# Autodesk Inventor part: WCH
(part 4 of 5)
hole "Díra1578" diameter "d14201" = 3.52941; stored, may be unused: countersink angle "d14205" = 90 deg, drill point angle "d14207" = 0 deg; dims "d14199" = 21, "d14200" = 241, "d14202" = 6, "d14203" = 4, "d14204" = 2, "d14206" = 8
hole "Díra1579" diameter "d14210" = 3.76471; stored, may be unused: countersink angle "d14214" = 90 deg, drill point angle "d14216" = 0 deg; dims "d14208" = 32, "d14209" = 241, "d14211" = 6, "d14212" = 4, "d14213" = 2, "d14215" = 8
hole "Díra1580" diameter "d14219" = 4.82353; stored, may be unused: countersink angle "d14223" = 90 deg, drill point angle "d14225" = 0 deg; dims "d14217" = 43, "d14218" = 241, "d14220" = 6, "d14221" = 4, "d14222" = 2, "d14224" = 8
hole "Díra1581" diameter "d14228" = 2.19608; stored, may be unused: countersink angle "d14232" = 90 deg, drill point angle "d14234" = 0 deg; dims "d14226" = 54, "d14227" = 241, "d14229" = 6, "d14230" = 4, "d14231" = 2, "d14233" = 8
hole "Díra1582" diameter "d14237" = 1.05882; stored, may be unused: countersink angle "d14241" = 90 deg, drill point angle "d14243" = 0 deg; dims "d14235" = 65, "d14236" = 241, "d14238" = 6, "d14239" = 4, "d14240" = 2, "d14242" = 8
hole "Díra1583" diameter "d14246" = 5.88235; stored, may be unused: countersink angle "d14250" = 90 deg, drill point angle "d14252" = 0 deg; dims "d14244" = 76, "d14245" = 241, "d14247" = 6, "d14248" = 4, "d14249" = 2, "d14251" = 8
hole "Díra1584" diameter "d14255" = 7.37255; stored, may be unused: countersink angle "d14259" = 90 deg, drill point angle "d14261" = 0 deg; dims "d14253" = 87, "d14254" = 241, "d14256" = 6, "d14257" = 4, "d14258" = 2, "d14260" = 8
hole "Díra1585" diameter "d14264" = 5.4902; stored, may be unused: countersink angle "d14268" = 90 deg, drill point angle "d14270" = 0 deg; dims "d14262" = 98, "d14263" = 241, "d14265" = 6, "d14266" = 4, "d14267" = 2, "d14269" = 8
hole "Díra1586" diameter "d14273" = 4.86275; stored, may be unused: countersink angle "d14277" = 90 deg, drill point angle "d14279" = 0 deg; dims "d14271" = 109, "d14272" = 241, "d14274" = 6, "d14275" = 4, "d14276" = 2, "d14278" = 8
hole "Díra1587" diameter "d14282" = 5.92157; stored, may be unused: countersink angle "d14286" = 90 deg, drill point angle "d14288" = 0 deg; dims "d14280" = 120, "d14281" = 241, "d14283" = 6, "d14284" = 4, "d14285" = 2, "d14287" = 8
hole "Díra1588" diameter "d14291" = 5.62092; stored, may be unused: countersink angle "d14295" = 90 deg, drill point angle "d14297" = 0 deg; dims "d14289" = 131, "d14290" = 241, "d14292" = 6, "d14293" = 4, "d14294" = 2, "d14296" = 8
hole "Díra1589" diameter "d14300" = 5.05882; stored, may be unused: countersink angle "d14304" = 90 deg, drill point angle "d14306" = 0 deg; dims "d14298" = 142, "d14299" = 241, "d14301" = 6, "d14302" = 4, "d14303" = 2, "d14305" = 8
hole "Díra1590" diameter "d14309" = 4.94118; stored, may be unused: countersink angle "d14313" = 90 deg, drill point angle "d14315" = 0 deg; dims "d14307" = 153, "d14308" = 241, "d14310" = 6, "d14311" = 4, "d14312" = 2, "d14314" = 8
hole "Díra1591" diameter "d14318" = 5.88235; stored, may be unused: countersink angle "d14322" = 90 deg, drill point angle "d14324" = 0 deg; dims "d14316" = 164, "d14317" = 241, "d14319" = 6, "d14320" = 4, "d14321" = 2, "d14323" = 8
hole "Díra1592" diameter "d14327" = 6.35294; stored, may be unused: countersink angle "d14331" = 90 deg, drill point angle "d14333" = 0 deg; dims "d14325" = 175, "d14326" = 241, "d14328" = 6, "d14329" = 4, "d14330" = 2, "d14332" = 8
hole "Díra1593" diameter "d14336" = 6.07843; stored, may be unused: countersink angle "d14340" = 90 deg, drill point angle "d14342" = 0 deg; dims "d14334" = 186, "d14335" = 241, "d14337" = 6, "d14338" = 4, "d14339" = 2, "d14341" = 8
hole "Díra1594" diameter "d14345" = 5.01961; stored, may be unused: countersink angle "d14349" = 90 deg, drill point angle "d14351" = 0 deg; dims "d14343" = 197, "d14344" = 241, "d14346" = 6, "d14347" = 4, "d14348" = 2, "d14350" = 8
hole "Díra1595" diameter "d14354" = 4.47059; stored, may be unused: countersink angle "d14358" = 90 deg, drill point angle "d14360" = 0 deg; dims "d14352" = 208, "d14353" = 241, "d14355" = 6, "d14356" = 4, "d14357" = 2, "d14359" = 8
hole "Díra1596" diameter "d14363" = 6.31372; stored, may be unused: countersink angle "d14367" = 90 deg, drill point angle "d14369" = 0 deg; dims "d14361" = 219, "d14362" = 241, "d14364" = 6, "d14365" = 4, "d14366" = 2, "d14368" = 8
hole "Díra1597" diameter "d14372" = 6.39216; stored, may be unused: countersink angle "d14376" = 90 deg, drill point angle "d14378" = 0 deg; dims "d14370" = 230, "d14371" = 241, "d14373" = 6, "d14374" = 4, "d14375" = 2, "d14377" = 8
hole "Díra1598" diameter "d14381" = 3.84314; stored, may be unused: countersink angle "d14385" = 90 deg, drill point angle "d14387" = 0 deg; dims "d14379" = 241, "d14380" = 241, "d14382" = 6, "d14383" = 4, "d14384" = 2, "d14386" = 8
hole "Díra1599" diameter "d14390" = 3.80392; stored, may be unused: countersink angle "d14394" = 90 deg, drill point angle "d14396" = 0 deg; dims "d14388" = 252, "d14389" = 241, "d14391" = 6, "d14392" = 4, "d14393" = 2, "d14395" = 8
hole "Díra1600" diameter "d14399" = 4.39216; stored, may be unused: countersink angle "d14403" = 90 deg, drill point angle "d14405" = 0 deg; dims "d14397" = 263, "d14398" = 241, "d14400" = 6, "d14401" = 4, "d14402" = 2, "d14404" = 8
hole "Díra1601" diameter "d14408" = 2.98039; stored, may be unused: countersink angle "d14412" = 90 deg, drill point angle "d14414" = 0 deg; dims "d14406" = 274, "d14407" = 241, "d14409" = 6, "d14410" = 4, "d14411" = 2, "d14413" = 8
hole "Díra1602" diameter "d14417" = 0.66667; stored, may be unused: countersink angle "d14421" = 90 deg, drill point angle "d14423" = 0 deg; dims "d14415" = 285, "d14416" = 241, "d14418" = 6, "d14419" = 4, "d14420" = 2, "d14422" = 8
hole "Díra1603" diameter "d14426" = 0.31372; stored, may be unused: countersink angle "d14430" = 90 deg, drill point angle "d14432" = 0 deg; dims "d14424" = 318, "d14425" = 241, "d14427" = 6, "d14428" = 4, "d14429" = 2, "d14431" = 8
hole "Díra1604" diameter "d14435" = 4.35294; stored, may be unused: countersink angle "d14439" = 90 deg, drill point angle "d14441" = 0 deg; dims "d14433" = 329, "d14434" = 241, "d14436" = 6, "d14437" = 4, "d14438" = 2, "d14440" = 8
hole "Díra1605" diameter "d14444" = 2.98039; stored, may be unused: countersink angle "d14448" = 90 deg, drill point angle "d14450" = 0 deg; dims "d14442" = 340, "d14443" = 241, "d14445" = 6, "d14446" = 4, "d14447" = 2, "d14449" = 8
hole "Díra1606" diameter "d14453" = 0.5098; stored, may be unused: countersink angle "d14457" = 90 deg, drill point angle "d14459" = 0 deg; dims "d14451" = 351, "d14452" = 241, "d14454" = 6, "d14455" = 4, "d14456" = 2, "d14458" = 8
hole "Díra1607" diameter "d14462" = 3.41176; stored, may be unused: countersink angle "d14466" = 90 deg, drill point angle "d14468" = 0 deg; dims "d14460" = 10, "d14461" = 252, "d14463" = 6, "d14464" = 4, "d14465" = 2, "d14467" = 8
hole "Díra1608" diameter "d14471" = 3.64706; stored, may be unused: countersink angle "d14475" = 90 deg, drill point angle "d14477" = 0 deg; dims "d14469" = 21, "d14470" = 252, "d14472" = 6, "d14473" = 4, "d14474" = 2, "d14476" = 8
hole "Díra1609" diameter "d14480" = 3.29412; stored, may be unused: countersink angle "d14484" = 90 deg, drill point angle "d14486" = 0 deg; dims "d14478" = 32, "d14479" = 252, "d14481" = 6, "d14482" = 4, "d14483" = 2, "d14485" = 8
hole "Díra1610" diameter "d14489" = 4.5098; stored, may be unused: countersink angle "d14493" = 90 deg, drill point angle "d14495" = 0 deg; dims "d14487" = 43, "d14488" = 252, "d14490" = 6, "d14491" = 4, "d14492" = 2, "d14494" = 8
hole "Díra1611" diameter "d14498" = 2.70588; stored, may be unused: countersink angle "d14502" = 90 deg, drill point angle "d14504" = 0 deg; dims "d14496" = 54, "d14497" = 252, "d14499" = 6, "d14500" = 4, "d14501" = 2, "d14503" = 8
hole "Díra1612" diameter "d14507" = 1.64706; stored, may be unused: countersink angle "d14511" = 90 deg, drill point angle "d14513" = 0 deg; dims "d14505" = 65, "d14506" = 252, "d14508" = 6, "d14509" = 4, "d14510" = 2, "d14512" = 8
hole "Díra1613" diameter "d14516" = 7.68628; stored, may be unused: countersink angle "d14520" = 90 deg, drill point angle "d14522" = 0 deg; dims "d14514" = 76, "d14515" = 252, "d14517" = 6, "d14518" = 4, "d14519" = 2, "d14521" = 8
hole "Díra1614" diameter "d14525" = 7.26797; stored, may be unused: countersink angle "d14529" = 90 deg, drill point angle "d14531" = 0 deg; dims "d14523" = 87, "d14524" = 252, "d14526" = 6, "d14527" = 4, "d14528" = 2, "d14530" = 8
hole "Díra1615" diameter "d14534" = 6.3268; stored, may be unused: countersink angle "d14538" = 90 deg, drill point angle "d14540" = 0 deg; dims "d14532" = 98, "d14533" = 252, "d14535" = 6, "d14536" = 4, "d14537" = 2, "d14539" = 8
hole "Díra1616" diameter "d14543" = 5.52941; stored, may be unused: countersink angle "d14547" = 90 deg, drill point angle "d14549" = 0 deg; dims "d14541" = 109, "d14542" = 252, "d14544" = 6, "d14545" = 4, "d14546" = 2, "d14548" = 8
hole "Díra1617" diameter "d14552" = 5.29412; stored, may be unused: countersink angle "d14556" = 90 deg, drill point angle "d14558" = 0 deg; dims "d14550" = 120, "d14551" = 252, "d14553" = 6, "d14554" = 4, "d14555" = 2, "d14557" = 8
hole "Díra1618" diameter "d14561" = 3.77778; stored, may be unused: countersink angle "d14565" = 90 deg, drill point angle "d14567" = 0 deg; dims "d14559" = 131, "d14560" = 252, "d14562" = 6, "d14563" = 4, "d14564" = 2, "d14566" = 8
hole "Díra1619" diameter "d14570" = 4.47059; stored, may be unused: countersink angle "d14574" = 90 deg, drill point angle "d14576" = 0 deg; dims "d14568" = 142, "d14569" = 252, "d14571" = 6, "d14572" = 4, "d14573" = 2, "d14575" = 8
hole "Díra1620" diameter "d14579" = 3.92157; stored, may be unused: countersink angle "d14583" = 90 deg, drill point angle "d14585" = 0 deg; dims "d14577" = 153, "d14578" = 252, "d14580" = 6, "d14581" = 4, "d14582" = 2, "d14584" = 8
hole "Díra1621" diameter "d14588" = 2.90196; stored, may be unused: countersink angle "d14592" = 90 deg, drill point angle "d14594" = 0 deg; dims "d14586" = 164, "d14587" = 252, "d14589" = 6, "d14590" = 4, "d14591" = 2, "d14593" = 8
hole "Díra1622" diameter "d14597" = 2.47059; stored, may be unused: countersink angle "d14601" = 90 deg, drill point angle "d14603" = 0 deg; dims "d14595" = 175, "d14596" = 252, "d14598" = 6, "d14599" = 4, "d14600" = 2, "d14602" = 8
hole "Díra1623" diameter "d14606" = 2.7451; stored, may be unused: countersink angle "d14610" = 90 deg, drill point angle "d14612" = 0 deg; dims "d14604" = 186, "d14605" = 252, "d14607" = 6, "d14608" = 4, "d14609" = 2, "d14611" = 8
hole "Díra1624" diameter "d14615" = 3.77778; stored, may be unused: countersink angle "d14619" = 90 deg, drill point angle "d14621" = 0 deg; dims "d14613" = 197, "d14614" = 252, "d14616" = 6, "d14617" = 4, "d14618" = 2, "d14620" = 8
hole "Díra1625" diameter "d14624" = 4.58824; stored, may be unused: countersink angle "d14628" = 90 deg, drill point angle "d14630" = 0 deg; dims "d14622" = 208, "d14623" = 252, "d14625" = 6, "d14626" = 4, "d14627" = 2, "d14629" = 8
hole "Díra1626" diameter "d14633" = 3.52941; stored, may be unused: countersink angle "d14637" = 90 deg, drill point angle "d14639" = 0 deg; dims "d14631" = 219, "d14632" = 252, "d14634" = 6, "d14635" = 4, "d14636" = 2, "d14638" = 8
hole "Díra1627" diameter "d14642" = 4.43137; stored, may be unused: countersink angle "d14646" = 90 deg, drill point angle "d14648" = 0 deg; dims "d14640" = 230, "d14641" = 252, "d14643" = 6, "d14644" = 4, "d14645" = 2, "d14647" = 8
hole "Díra1628" diameter "d14651" = 6.35294; stored, may be unused: countersink angle "d14655" = 90 deg, drill point angle "d14657" = 0 deg; dims "d14649" = 241, "d14650" = 252, "d14652" = 6, "d14653" = 4, "d14654" = 2, "d14656" = 8
hole "Díra1629" diameter "d14660" = 5.88235; stored, may be unused: countersink angle "d14664" = 90 deg, drill point angle "d14666" = 0 deg; dims "d14658" = 252, "d14659" = 252, "d14661" = 6, "d14662" = 4, "d14663" = 2, "d14665" = 8
hole "Díra1630" diameter "d14669" = 4.78431; stored, may be unused: countersink angle "d14673" = 90 deg, drill point angle "d14675" = 0 deg; dims "d14667" = 263, "d14668" = 252, "d14670" = 6, "d14671" = 4, "d14672" = 2, "d14674" = 8
hole "Díra1631" diameter "d14678" = 4.58824; stored, may be unused: countersink angle "d14682" = 90 deg, drill point angle "d14684" = 0 deg; dims "d14676" = 274, "d14677" = 252, "d14679" = 6, "d14680" = 4, "d14681" = 2, "d14683" = 8
hole "Díra1632" diameter "d14687" = 1.4902; stored, may be unused: countersink angle "d14691" = 90 deg, drill point angle "d14693" = 0 deg; dims "d14685" = 285, "d14686" = 252, "d14688" = 6, "d14689" = 4, "d14690" = 2, "d14692" = 8
hole "Díra1633" diameter "d14696" = 3.52941; stored, may be unused: countersink angle "d14700" = 90 deg, drill point angle "d14702" = 0 deg; dims "d14694" = 329, "d14695" = 252, "d14697" = 6, "d14698" = 4, "d14699" = 2, "d14701" = 8
hole "Díra1634" diameter "d14705" = 1.72549; stored, may be unused: countersink angle "d14709" = 90 deg, drill point angle "d14711" = 0 deg; dims "d14703" = 340, "d14704" = 252, "d14706" = 6, "d14707" = 4, "d14708" = 2, "d14710" = 8
hole "Díra1635" diameter "d14714" = 3.64706; stored, may be unused: countersink angle "d14718" = 90 deg, drill point angle "d14720" = 0 deg; dims "d14712" = 10, "d14713" = 263, "d14715" = 6, "d14716" = 4, "d14717" = 2, "d14719" = 8
hole "Díra1636" diameter "d14723" = 3.64706; stored, may be unused: countersink angle "d14727" = 90 deg, drill point angle "d14729" = 0 deg; dims "d14721" = 21, "d14722" = 263, "d14724" = 6, "d14725" = 4, "d14726" = 2, "d14728" = 8
hole "Díra1637" diameter "d14732" = 3.80392; stored, may be unused: countersink angle "d14736" = 90 deg, drill point angle "d14738" = 0 deg; dims "d14730" = 32, "d14731" = 263, "d14733" = 6, "d14734" = 4, "d14735" = 2, "d14737" = 8
hole "Díra1638" diameter "d14741" = 2.98039; stored, may be unused: countersink angle "d14745" = 90 deg, drill point angle "d14747" = 0 deg; dims "d14739" = 43, "d14740" = 263, "d14742" = 6, "d14743" = 4, "d14744" = 2, "d14746" = 8
hole "Díra1639" diameter "d14750" = 1.64706; stored, may be unused: countersink angle "d14754" = 90 deg, drill point angle "d14756" = 0 deg; dims "d14748" = 54, "d14749" = 263, "d14751" = 6, "d14752" = 4, "d14753" = 2, "d14755" = 8
hole "Díra1640" diameter "d14759" = 2.94118; stored, may be unused: countersink angle "d14763" = 90 deg, drill point angle "d14765" = 0 deg; dims "d14757" = 65, "d14758" = 263, "d14760" = 6, "d14761" = 4, "d14762" = 2, "d14764" = 8
hole "Díra1641" diameter "d14768" = 9.84314; stored, may be unused: countersink angle "d14772" = 90 deg, drill point angle "d14774" = 0 deg; dims "d14766" = 76, "d14767" = 263, "d14769" = 6, "d14770" = 4, "d14771" = 2, "d14773" = 8
hole "Díra1642" diameter "d14777" = 8.90196; stored, may be unused: countersink angle "d14781" = 90 deg, drill point angle "d14783" = 0 deg; dims "d14775" = 87, "d14776" = 263, "d14778" = 6, "d14779" = 4, "d14780" = 2, "d14782" = 8
hole "Díra1643" diameter "d14786" = 7.15033; stored, may be unused: countersink angle "d14790" = 90 deg, drill point angle "d14792" = 0 deg; dims "d14784" = 98, "d14785" = 263, "d14787" = 6, "d14788" = 4, "d14789" = 2, "d14791" = 8
hole "Díra1644" diameter "d14795" = 6.31372; stored, may be unused: countersink angle "d14799" = 90 deg, drill point angle "d14801" = 0 deg; dims "d14793" = 109, "d14794" = 263, "d14796" = 6, "d14797" = 4, "d14798" = 2, "d14800" = 8
hole "Díra1645" diameter "d14804" = 5.83007; stored, may be unused: countersink angle "d14808" = 90 deg, drill point angle "d14810" = 0 deg; dims "d14802" = 120, "d14803" = 263, "d14805" = 6, "d14806" = 4, "d14807" = 2, "d14809" = 8
hole "Díra1646" diameter "d14813" = 4.62745; stored, may be unused: countersink angle "d14817" = 90 deg, drill point angle "d14819" = 0 deg; dims "d14811" = 131, "d14812" = 263, "d14814" = 6, "d14815" = 4, "d14816" = 2, "d14818" = 8
hole "Díra1647" diameter "d14822" = 3.4902; stored, may be unused: countersink angle "d14826" = 90 deg, drill point angle "d14828" = 0 deg; dims "d14820" = 142, "d14821" = 263, "d14823" = 6, "d14824" = 4, "d14825" = 2, "d14827" = 8
hole "Díra1648" diameter "d14831" = 3.17647; stored, may be unused: countersink angle "d14835" = 90 deg, drill point angle "d14837" = 0 deg; dims "d14829" = 153, "d14830" = 263, "d14832" = 6, "d14833" = 4, "d14834" = 2, "d14836" = 8
hole "Díra1649" diameter "d14840" = 2.7451; stored, may be unused: countersink angle "d14844" = 90 deg, drill point angle "d14846" = 0 deg; dims "d14838" = 164, "d14839" = 263, "d14841" = 6, "d14842" = 4, "d14843" = 2, "d14845" = 8
hole "Díra1650" diameter "d14849" = 2.7451; stored, may be unused: countersink angle "d14853" = 90 deg, drill point angle "d14855" = 0 deg; dims "d14847" = 175, "d14848" = 263, "d14850" = 6, "d14851" = 4, "d14852" = 2, "d14854" = 8
hole "Díra1651" diameter "d14858" = 3.09804; stored, may be unused: countersink angle "d14862" = 90 deg, drill point angle "d14864" = 0 deg; dims "d14856" = 186, "d14857" = 263, "d14859" = 6, "d14860" = 4, "d14861" = 2, "d14863" = 8
hole "Díra1652" diameter "d14867" = 3.5817; stored, may be unused: countersink angle "d14871" = 90 deg, drill point angle "d14873" = 0 deg; dims "d14865" = 197, "d14866" = 263, "d14868" = 6, "d14869" = 4, "d14870" = 2, "d14872" = 8
hole "Díra1653" diameter "d14876" = 3.4902; stored, may be unused: countersink angle "d14880" = 90 deg, drill point angle "d14882" = 0 deg; dims "d14874" = 208, "d14875" = 263, "d14877" = 6, "d14878" = 4, "d14879" = 2, "d14881" = 8
hole "Díra1654" diameter "d14885" = 3.52941; stored, may be unused: countersink angle "d14889" = 90 deg, drill point angle "d14891" = 0 deg; dims "d14883" = 219, "d14884" = 263, "d14886" = 6, "d14887" = 4, "d14888" = 2, "d14890" = 8
hole "Díra1655" diameter "d14894" = 3.80392; stored, may be unused: countersink angle "d14898" = 90 deg, drill point angle "d14900" = 0 deg; dims "d14892" = 230, "d14893" = 263, "d14895" = 6, "d14896" = 4, "d14897" = 2, "d14899" = 8
hole "Díra1656" diameter "d14903" = 4.18301; stored, may be unused: countersink angle "d14907" = 90 deg, drill point angle "d14909" = 0 deg; dims "d14901" = 241, "d14902" = 263, "d14904" = 6, "d14905" = 4, "d14906" = 2, "d14908" = 8
hole "Díra1657" diameter "d14912" = 5.5817; stored, may be unused: countersink angle "d14916" = 90 deg, drill point angle "d14918" = 0 deg; dims "d14910" = 252, "d14911" = 263, "d14913" = 6, "d14914" = 4, "d14915" = 2, "d14917" = 8
hole "Díra1658" diameter "d14921" = 6.23529; stored, may be unused: countersink angle "d14925" = 90 deg, drill point angle "d14927" = 0 deg; dims "d14919" = 263, "d14920" = 263, "d14922" = 6, "d14923" = 4, "d14924" = 2, "d14926" = 8
hole "Díra1659" diameter "d14930" = 5.17647; stored, may be unused: countersink angle "d14934" = 90 deg, drill point angle "d14936" = 0 deg; dims "d14928" = 274, "d14929" = 263, "d14931" = 6, "d14932" = 4, "d14933" = 2, "d14935" = 8
hole "Díra1660" diameter "d14939" = 1.88235; stored, may be unused: countersink angle "d14943" = 90 deg, drill point angle "d14945" = 0 deg; dims "d14937" = 285, "d14938" = 263, "d14940" = 6, "d14941" = 4, "d14942" = 2, "d14944" = 8
hole "Díra1661" diameter "d14948" = 0.5098; stored, may be unused: countersink angle "d14952" = 90 deg, drill point angle "d14954" = 0 deg; dims "d14946" = 329, "d14947" = 263, "d14949" = 6, "d14950" = 4, "d14951" = 2, "d14953" = 8
hole "Díra1662" diameter "d14957" = 4.19608; stored, may be unused: countersink angle "d14961" = 90 deg, drill point angle "d14963" = 0 deg; dims "d14955" = 10, "d14956" = 274, "d14958" = 6, "d14959" = 4, "d14960" = 2, "d14962" = 8
hole "Díra1663" diameter "d14966" = 2.94118; stored, may be unused: countersink angle "d14970" = 90 deg, drill point angle "d14972" = 0 deg; dims "d14964" = 21, "d14965" = 274, "d14967" = 6, "d14968" = 4, "d14969" = 2, "d14971" = 8
hole "Díra1664" diameter "d14975" = 3.52941; stored, may be unused: countersink angle "d14979" = 90 deg, drill point angle "d14981" = 0 deg; dims "d14973" = 32, "d14974" = 274, "d14976" = 6, "d14977" = 4, "d14978" = 2, "d14980" = 8
hole "Díra1665" diameter "d14984" = 6.98039; stored, may be unused: countersink angle "d14988" = 90 deg, drill point angle "d14990" = 0 deg; dims "d14982" = 43, "d14983" = 274, "d14985" = 6, "d14986" = 4, "d14987" = 2, "d14989" = 8
hole "Díra1666" diameter "d14993" = 8.82353; stored, may be unused: countersink angle "d14997" = 90 deg, drill point angle "d14999" = 0 deg; dims "d14991" = 54, "d14992" = 274, "d14994" = 6, "d14995" = 4, "d14996" = 2, "d14998" = 8
hole "Díra1667" diameter "d15002" = 10; stored, may be unused: countersink angle "d15006" = 90 deg, drill point angle "d15008" = 0 deg; dims "d15000" = 65, "d15001" = 274, "d15003" = 6, "d15004" = 4, "d15005" = 2, "d15007" = 8
hole "Díra1668" diameter "d15011" = 10; stored, may be unused: countersink angle "d15015" = 90 deg, drill point angle "d15017" = 0 deg; dims "d15009" = 76, "d15010" = 274, "d15012" = 6, "d15013" = 4, "d15014" = 2, "d15016" = 8
hole "Díra1669" diameter "d15020" = 10; stored, may be unused: countersink angle "d15024" = 90 deg, drill point angle "d15026" = 0 deg; dims "d15018" = 87, "d15019" = 274, "d15021" = 6, "d15022" = 4, "d15023" = 2, "d15025" = 8
hole "Díra1670" diameter "d15029" = 9.41177; stored, may be unused: countersink angle "d15033" = 90 deg, drill point angle "d15035" = 0 deg; dims "d15027" = 98, "d15028" = 274, "d15030" = 6, "d15031" = 4, "d15032" = 2, "d15034" = 8
hole "Díra1671" diameter "d15038" = 8.62745; stored, may be unused: countersink angle "d15042" = 90 deg, drill point angle "d15044" = 0 deg; dims "d15036" = 109, "d15037" = 274, "d15039" = 6, "d15040" = 4, "d15041" = 2, "d15043" = 8
hole "Díra1672" diameter "d15047" = 7.80392; stored, may be unused: countersink angle "d15051" = 90 deg, drill point angle "d15053" = 0 deg; dims "d15045" = 120, "d15046" = 274, "d15048" = 6, "d15049" = 4, "d15050" = 2, "d15052" = 8
hole "Díra1673" diameter "d15056" = 7.15033; stored, may be unused: countersink angle "d15060" = 90 deg, drill point angle "d15062" = 0 deg; dims "d15054" = 131, "d15055" = 274, "d15057" = 6, "d15058" = 4, "d15059" = 2, "d15061" = 8
hole "Díra1674" diameter "d15065" = 6.47059; stored, may be unused: countersink angle "d15069" = 90 deg, drill point angle "d15071" = 0 deg; dims "d15063" = 142, "d15064" = 274, "d15066" = 6, "d15067" = 4, "d15068" = 2, "d15070" = 8
hole "Díra1675" diameter "d15074" = 6.07843; stored, may be unused: countersink angle "d15078" = 90 deg, drill point angle "d15080" = 0 deg; dims "d15072" = 153, "d15073" = 274, "d15075" = 6, "d15076" = 4, "d15077" = 2, "d15079" = 8
hole "Díra1676" diameter "d15083" = 5.64706; stored, may be unused: countersink angle "d15087" = 90 deg, drill point angle "d15089" = 0 deg; dims "d15081" = 164, "d15082" = 274, "d15084" = 6, "d15085" = 4, "d15086" = 2, "d15088" = 8
hole "Díra1677" diameter "d15092" = 5.41177; stored, may be unused: countersink angle "d15096" = 90 deg, drill point angle "d15098" = 0 deg; dims "d15090" = 175, "d15091" = 274, "d15093" = 6, "d15094" = 4, "d15095" = 2, "d15097" = 8
hole "Díra1678" diameter "d15101" = 5.64706; stored, may be unused: countersink angle "d15105" = 90 deg, drill point angle "d15107" = 0 deg; dims "d15099" = 186, "d15100" = 274, "d15102" = 6, "d15103" = 4, "d15104" = 2, "d15106" = 8
hole "Díra1679" diameter "d15110" = 6.16993; stored, may be unused: countersink angle "d15114" = 90 deg, drill point angle "d15116" = 0 deg; dims "d15108" = 197, "d15109" = 274, "d15111" = 6, "d15112" = 4, "d15113" = 2, "d15115" = 8
hole "Díra1680" diameter "d15119" = 6.28758; stored, may be unused: countersink angle "d15123" = 90 deg, drill point angle "d15125" = 0 deg; dims "d15117" = 208, "d15118" = 274, "d15120" = 6, "d15121" = 4, "d15122" = 2, "d15124" = 8
hole "Díra1681" diameter "d15128" = 6.11765; stored, may be unused: countersink angle "d15132" = 90 deg, drill point angle "d15134" = 0 deg; dims "d15126" = 219, "d15127" = 274, "d15129" = 6, "d15130" = 4, "d15131" = 2, "d15133" = 8
hole "Díra1682" diameter "d15137" = 6.11765; stored, may be unused: countersink angle "d15141" = 90 deg, drill point angle "d15143" = 0 deg; dims "d15135" = 230, "d15136" = 274, "d15138" = 6, "d15139" = 4, "d15140" = 2, "d15142" = 8
hole "Díra1683" diameter "d15146" = 6.03922; stored, may be unused: countersink angle "d15150" = 90 deg, drill point angle "d15152" = 0 deg; dims "d15144" = 241, "d15145" = 274, "d15147" = 6, "d15148" = 4, "d15149" = 2, "d15151" = 8
hole "Díra1684" diameter "d15155" = 6.31372; stored, may be unused: countersink angle "d15159" = 90 deg, drill point angle "d15161" = 0 deg; dims "d15153" = 252, "d15154" = 274, "d15156" = 6, "d15157" = 4, "d15158" = 2, "d15160" = 8
hole "Díra1685" diameter "d15164" = 6.58824; stored, may be unused: countersink angle "d15168" = 90 deg, drill point angle "d15170" = 0 deg; dims "d15162" = 263, "d15163" = 274, "d15165" = 6, "d15166" = 4, "d15167" = 2, "d15169" = 8
hole "Díra1686" diameter "d15173" = 5.72549; stored, may be unused: countersink angle "d15177" = 90 deg, drill point angle "d15179" = 0 deg; dims "d15171" = 274, "d15172" = 274, "d15174" = 6, "d15175" = 4, "d15176" = 2, "d15178" = 8
hole "Díra1687" diameter "d15182" = 4.07843; stored, may be unused: countersink angle "d15186" = 90 deg, drill point angle "d15188" = 0 deg; dims "d15180" = 285, "d15181" = 274, "d15183" = 6, "d15184" = 4, "d15185" = 2, "d15187" = 8
hole "Díra1688" diameter "d15191" = 2.94118; stored, may be unused: countersink angle "d15195" = 90 deg, drill point angle "d15197" = 0 deg; dims "d15189" = 10, "d15190" = 285, "d15192" = 6, "d15193" = 4, "d15194" = 2, "d15196" = 8
hole "Díra1689" diameter "d15200" = 4; stored, may be unused: countersink angle "d15204" = 90 deg, drill point angle "d15206" = 0 deg; dims "d15198" = 21, "d15199" = 285, "d15201" = 6, "d15202" = 4, "d15203" = 2, "d15205" = 8
hole "Díra1690" diameter "d15209" = 9.45098; stored, may be unused: countersink angle "d15213" = 90 deg, drill point angle "d15215" = 0 deg; dims "d15207" = 32, "d15208" = 285, "d15210" = 6, "d15211" = 4, "d15212" = 2, "d15214" = 8
hole "Díra1691" diameter "d15218" = 10; stored, may be unused: countersink angle "d15222" = 90 deg, drill point angle "d15224" = 0 deg; dims "d15216" = 43, "d15217" = 285, "d15219" = 6, "d15220" = 4, "d15221" = 2, "d15223" = 8
hole "Díra1692" diameter "d15227" = 10; stored, may be unused: countersink angle "d15231" = 90 deg, drill point angle "d15233" = 0 deg; dims "d15225" = 54, "d15226" = 285, "d15228" = 6, "d15229" = 4, "d15230" = 2, "d15232" = 8
hole "Díra1693" diameter "d15236" = 10; stored, may be unused: countersink angle "d15240" = 90 deg, drill point angle "d15242" = 0 deg; dims "d15234" = 65, "d15235" = 285, "d15237" = 6, "d15238" = 4, "d15239" = 2, "d15241" = 8
hole "Díra1694" diameter "d15245" = 10; stored, may be unused: countersink angle "d15249" = 90 deg, drill point angle "d15251" = 0 deg; dims "d15243" = 76, "d15244" = 285, "d15246" = 6, "d15247" = 4, "d15248" = 2, "d15250" = 8
hole "Díra1695" diameter "d15254" = 10; stored, may be unused: countersink angle "d15258" = 90 deg, drill point angle "d15260" = 0 deg; dims "d15252" = 87, "d15253" = 285, "d15255" = 6, "d15256" = 4, "d15257" = 2, "d15259" = 8
hole "Díra1696" diameter "d15263" = 10; stored, may be unused: countersink angle "d15267" = 90 deg, drill point angle "d15269" = 0 deg; dims "d15261" = 98, "d15262" = 285, "d15264" = 6, "d15265" = 4, "d15266" = 2, "d15268" = 8
hole "Díra1697" diameter "d15272" = 10; stored, may be unused: countersink angle "d15276" = 90 deg, drill point angle "d15278" = 0 deg; dims "d15270" = 109, "d15271" = 285, "d15273" = 6, "d15274" = 4, "d15275" = 2, "d15277" = 8
hole "Díra1698" diameter "d15281" = 10; stored, may be unused: countersink angle "d15285" = 90 deg, drill point angle "d15287" = 0 deg; dims "d15279" = 120, "d15280" = 285, "d15282" = 6, "d15283" = 4, "d15284" = 2, "d15286" = 8
hole "Díra1699" diameter "d15290" = 10; stored, may be unused: countersink angle "d15294" = 90 deg, drill point angle "d15296" = 0 deg; dims "d15288" = 131, "d15289" = 285, "d15291" = 6, "d15292" = 4, "d15293" = 2, "d15295" = 8
hole "Díra1700" diameter "d15299" = 9.92157; stored, may be unused: countersink angle "d15303" = 90 deg, drill point angle "d15305" = 0 deg; dims "d15297" = 142, "d15298" = 285, "d15300" = 6, "d15301" = 4, "d15302" = 2, "d15304" = 8
hole "Díra1701" diameter "d15308" = 9.80392; stored, may be unused: countersink angle "d15312" = 90 deg, drill point angle "d15314" = 0 deg; dims "d15306" = 153, "d15307" = 285, "d15309" = 6, "d15310" = 4, "d15311" = 2, "d15313" = 8
hole "Díra1702" diameter "d15317" = 9.68628; stored, may be unused: countersink angle "d15321" = 90 deg, drill point angle "d15323" = 0 deg; dims "d15315" = 164, "d15316" = 285, "d15318" = 6, "d15319" = 4, "d15320" = 2, "d15322" = 8
hole "Díra1703" diameter "d15326" = 9.52941; stored, may be unused: countersink angle "d15330" = 90 deg, drill point angle "d15332" = 0 deg; dims "d15324" = 175, "d15325" = 285, "d15327" = 6, "d15328" = 4, "d15329" = 2, "d15331" = 8
hole "Díra1704" diameter "d15335" = 9.60784; stored, may be unused: countersink angle "d15339" = 90 deg, drill point angle "d15341" = 0 deg; dims "d15333" = 186, "d15334" = 285, "d15336" = 6, "d15337" = 4, "d15338" = 2, "d15340" = 8
hole "Díra1705" diameter "d15344" = 9.68628; stored, may be unused: countersink angle "d15348" = 90 deg, drill point angle "d15350" = 0 deg; dims "d15342" = 197, "d15343" = 285, "d15345" = 6, "d15346" = 4, "d15347" = 2, "d15349" = 8
hole "Díra1706" diameter "d15353" = 9.68628; stored, may be unused: countersink angle "d15357" = 90 deg, drill point angle "d15359" = 0 deg; dims "d15351" = 208, "d15352" = 285, "d15354" = 6, "d15355" = 4, "d15356" = 2, "d15358" = 8
hole "Díra1707" diameter "d15362" = 9.68628; stored, may be unused: countersink angle "d15366" = 90 deg, drill point angle "d15368" = 0 deg; dims "d15360" = 219, "d15361" = 285, "d15363" = 6, "d15364" = 4, "d15365" = 2, "d15367" = 8
hole "Díra1708" diameter "d15371" = 9.68628; stored, may be unused: countersink angle "d15375" = 90 deg, drill point angle "d15377" = 0 deg; dims "d15369" = 230, "d15370" = 285, "d15372" = 6, "d15373" = 4, "d15374" = 2, "d15376" = 8
hole "Díra1709" diameter "d15380" = 9.52941; stored, may be unused: countersink angle "d15384" = 90 deg, drill point angle "d15386" = 0 deg; dims "d15378" = 241, "d15379" = 285, "d15381" = 6, "d15382" = 4, "d15383" = 2, "d15385" = 8
hole "Díra1710" diameter "d15389" = 9.41177; stored, may be unused: countersink angle "d15393" = 90 deg, drill point angle "d15395" = 0 deg; dims "d15387" = 252, "d15388" = 285, "d15390" = 6, "d15391" = 4, "d15392" = 2, "d15394" = 8
hole "Díra1711" diameter "d15398" = 9.01961; stored, may be unused: countersink angle "d15402" = 90 deg, drill point angle "d15404" = 0 deg; dims "d15396" = 263, "d15397" = 285, "d15399" = 6, "d15400" = 4, "d15401" = 2, "d15403" = 8
hole "Díra1712" diameter "d15407" = 7.92157; stored, may be unused: countersink angle "d15411" = 90 deg, drill point angle "d15413" = 0 deg; dims "d15405" = 274, "d15406" = 285, "d15408" = 6, "d15409" = 4, "d15410" = 2, "d15412" = 8
hole "Díra1713" diameter "d15416" = 7.29412; stored, may be unused: countersink angle "d15420" = 90 deg, drill point angle "d15422" = 0 deg; dims "d15414" = 285, "d15415" = 285, "d15417" = 6, "d15418" = 4, "d15419" = 2, "d15421" = 8
hole "Díra1714" diameter "d15425" = 2.66667; stored, may be unused: countersink angle "d15429" = 90 deg, drill point angle "d15431" = 0 deg; dims "d15423" = 296, "d15424" = 285, "d15426" = 6, "d15427" = 4, "d15428" = 2, "d15430" = 8
hole "Díra1715" diameter "d15434" = 3.72549; stored, may be unused: countersink angle "d15438" = 90 deg, drill point angle "d15440" = 0 deg; dims "d15432" = 10, "d15433" = 296, "d15435" = 6, "d15436" = 4, "d15437" = 2, "d15439" = 8
hole "Díra1716" diameter "d15443" = 9.45098; stored, may be unused: countersink angle "d15447" = 90 deg, drill point angle "d15449" = 0 deg; dims "d15441" = 21, "d15442" = 296, "d15444" = 6, "d15445" = 4, "d15446" = 2, "d15448" = 8
hole "Díra1717" diameter "d15452" = 10; stored, may be unused: countersink angle "d15456" = 90 deg, drill point angle "d15458" = 0 deg; dims "d15450" = 32, "d15451" = 296, "d15453" = 6, "d15454" = 4, "d15455" = 2, "d15457" = 8
hole "Díra1718" diameter "d15461" = 10; stored, may be unused: countersink angle "d15465" = 90 deg, drill point angle "d15467" = 0 deg; dims "d15459" = 43, "d15460" = 296, "d15462" = 6, "d15463" = 4, "d15464" = 2, "d15466" = 8
hole "Díra1719" diameter "d15470" = 10; stored, may be unused: countersink angle "d15474" = 90 deg, drill point angle "d15476" = 0 deg; dims "d15468" = 54, "d15469" = 296, "d15471" = 6, "d15472" = 4, "d15473" = 2, "d15475" = 8
hole "Díra1720" diameter "d15479" = 10; stored, may be unused: countersink angle "d15483" = 90 deg, drill point angle "d15485" = 0 deg; dims "d15477" = 65, "d15478" = 296, "d15480" = 6, "d15481" = 4, "d15482" = 2, "d15484" = 8
hole "Díra1721" diameter "d15488" = 10; stored, may be unused: countersink angle "d15492" = 90 deg, drill point angle "d15494" = 0 deg; dims "d15486" = 76, "d15487" = 296, "d15489" = 6, "d15490" = 4, "d15491" = 2, "d15493" = 8
hole "Díra1722" diameter "d15497" = 10; stored, may be unused: countersink angle "d15501" = 90 deg, drill point angle "d15503" = 0 deg; dims "d15495" = 87, "d15496" = 296, "d15498" = 6, "d15499" = 4, "d15500" = 2, "d15502" = 8
hole "Díra1723" diameter "d15506" = 10; stored, may be unused: countersink angle "d15510" = 90 deg, drill point angle "d15512" = 0 deg; dims "d15504" = 98, "d15505" = 296, "d15507" = 6, "d15508" = 4, "d15509" = 2, "d15511" = 8
hole "Díra1724" diameter "d15515" = 10; stored, may be unused: countersink angle "d15519" = 90 deg, drill point angle "d15521" = 0 deg; dims "d15513" = 109, "d15514" = 296, "d15516" = 6, "d15517" = 4, "d15518" = 2, "d15520" = 8
hole "Díra1725" diameter "d15524" = 10; stored, may be unused: countersink angle "d15528" = 90 deg, drill point angle "d15530" = 0 deg; dims "d15522" = 120, "d15523" = 296, "d15525" = 6, "d15526" = 4, "d15527" = 2, "d15529" = 8
hole "Díra1726" diameter "d15533" = 10; stored, may be unused: countersink angle "d15537" = 90 deg, drill point angle "d15539" = 0 deg; dims "d15531" = 131, "d15532" = 296, "d15534" = 6, "d15535" = 4, "d15536" = 2, "d15538" = 8
hole "Díra1727" diameter "d15542" = 10; stored, may be unused: countersink angle "d15546" = 90 deg, drill point angle "d15548" = 0 deg; dims "d15540" = 142, "d15541" = 296, "d15543" = 6, "d15544" = 4, "d15545" = 2, "d15547" = 8
hole "Díra1728" diameter "d15551" = 10; stored, may be unused: countersink angle "d15555" = 90 deg, drill point angle "d15557" = 0 deg; dims "d15549" = 153, "d15550" = 296, "d15552" = 6, "d15553" = 4, "d15554" = 2, "d15556" = 8
hole "Díra1729" diameter "d15560" = 10; stored, may be unused: countersink angle "d15564" = 90 deg, drill point angle "d15566" = 0 deg; dims "d15558" = 164, "d15559" = 296, "d15561" = 6, "d15562" = 4, "d15563" = 2, "d15565" = 8
hole "Díra1730" diameter "d15569" = 10; stored, may be unused: countersink angle "d15573" = 90 deg, drill point angle "d15575" = 0 deg; dims "d15567" = 175, "d15568" = 296, "d15570" = 6, "d15571" = 4, "d15572" = 2, "d15574" = 8
hole "Díra1731" diameter "d15578" = 10; stored, may be unused: countersink angle "d15582" = 90 deg, drill point angle "d15584" = 0 deg; dims "d15576" = 186, "d15577" = 296, "d15579" = 6, "d15580" = 4, "d15581" = 2, "d15583" = 8
hole "Díra1732" diameter "d15587" = 10; stored, may be unused: countersink angle "d15591" = 90 deg, drill point angle "d15593" = 0 deg; dims "d15585" = 197, "d15586" = 296, "d15588" = 6, "d15589" = 4, "d15590" = 2, "d15592" = 8
hole "Díra1733" diameter "d15596" = 10; stored, may be unused: countersink angle "d15600" = 90 deg, drill point angle "d15602" = 0 deg; dims "d15594" = 208, "d15595" = 296, "d15597" = 6, "d15598" = 4, "d15599" = 2, "d15601" = 8
hole "Díra1734" diameter "d15605" = 10; stored, may be unused: countersink angle "d15609" = 90 deg, drill point angle "d15611" = 0 deg; dims "d15603" = 219, "d15604" = 296, "d15606" = 6, "d15607" = 4, "d15608" = 2, "d15610" = 8
hole "Díra1735" diameter "d15614" = 10; stored, may be unused: countersink angle "d15618" = 90 deg, drill point angle "d15620" = 0 deg; dims "d15612" = 230, "d15613" = 296, "d15615" = 6, "d15616" = 4, "d15617" = 2, "d15619" = 8
hole "Díra1736" diameter "d15623" = 10; stored, may be unused: countersink angle "d15627" = 90 deg, drill point angle "d15629" = 0 deg; dims "d15621" = 241, "d15622" = 296, "d15624" = 6, "d15625" = 4, "d15626" = 2, "d15628" = 8
hole "Díra1737" diameter "d15632" = 10; stored, may be unused: countersink angle "d15636" = 90 deg, drill point angle "d15638" = 0 deg; dims "d15630" = 252, "d15631" = 296, "d15633" = 6, "d15634" = 4, "d15635" = 2, "d15637" = 8
hole "Díra1738" diameter "d15641" = 10; stored, may be unused: countersink angle "d15645" = 90 deg, drill point angle "d15647" = 0 deg; dims "d15639" = 263, "d15640" = 296, "d15642" = 6, "d15643" = 4, "d15644" = 2, "d15646" = 8
hole "Díra1739" diameter "d15650" = 10; stored, may be unused: countersink angle "d15654" = 90 deg, drill point angle "d15656" = 0 deg; dims "d15648" = 274, "d15649" = 296, "d15651" = 6, "d15652" = 4, "d15653" = 2, "d15655" = 8
hole "Díra1740" diameter "d15659" = 10; stored, may be unused: countersink angle "d15663" = 90 deg, drill point angle "d15665" = 0 deg; dims "d15657" = 285, "d15658" = 296, "d15660" = 6, "d15661" = 4, "d15662" = 2, "d15664" = 8
hole "Díra1741" diameter "d15668" = 10; stored, may be unused: countersink angle "d15672" = 90 deg, drill point angle "d15674" = 0 deg; dims "d15666" = 296, "d15667" = 296, "d15669" = 6, "d15670" = 4, "d15671" = 2, "d15673" = 8
hole "Díra1742" diameter "d15677" = 9.80392; stored, may be unused: countersink angle "d15681" = 90 deg, drill point angle "d15683" = 0 deg; dims "d15675" = 307, "d15676" = 296, "d15678" = 6, "d15679" = 4, "d15680" = 2, "d15682" = 8
hole "Díra1743" diameter "d15686" = 6.31372; stored, may be unused: countersink angle "d15690" = 90 deg, drill point angle "d15692" = 0 deg; dims "d15684" = 318, "d15685" = 296, "d15687" = 6, "d15688" = 4, "d15689" = 2, "d15691" = 8
hole "Díra1744" diameter "d15695" = 1.05882; stored, may be unused: countersink angle "d15699" = 90 deg, drill point angle "d15701" = 0 deg; dims "d15693" = 329, "d15694" = 296, "d15696" = 6, "d15697" = 4, "d15698" = 2, "d15700" = 8
hole "Díra1745" diameter "d15704" = 5.68628; stored, may be unused: countersink angle "d15708" = 90 deg, drill point angle "d15710" = 0 deg; dims "d15702" = 10, "d15703" = 307, "d15705" = 6, "d15706" = 4, "d15707" = 2, "d15709" = 8
hole "Díra1746" diameter "d15713" = 10; stored, may be unused: countersink angle "d15717" = 90 deg, drill point angle "d15719" = 0 deg; dims "d15711" = 21, "d15712" = 307, "d15714" = 6, "d15715" = 4, "d15716" = 2, "d15718" = 8
hole "Díra1747" diameter "d15722" = 10; stored, may be unused: countersink angle "d15726" = 90 deg, drill point angle "d15728" = 0 deg; dims "d15720" = 32, "d15721" = 307, "d15723" = 6, "d15724" = 4, "d15725" = 2, "d15727" = 8
hole "Díra1748" diameter "d15731" = 10; stored, may be unused: countersink angle "d15735" = 90 deg, drill point angle "d15737" = 0 deg; dims "d15729" = 43, "d15730" = 307, "d15732" = 6, "d15733" = 4, "d15734" = 2, "d15736" = 8
hole "Díra1749" diameter "d15740" = 10; stored, may be unused: countersink angle "d15744" = 90 deg, drill point angle "d15746" = 0 deg; dims "d15738" = 54, "d15739" = 307, "d15741" = 6, "d15742" = 4, "d15743" = 2, "d15745" = 8
hole "Díra1750" diameter "d15749" = 10; stored, may be unused: countersink angle "d15753" = 90 deg, drill point angle "d15755" = 0 deg; dims "d15747" = 65, "d15748" = 307, "d15750" = 6, "d15751" = 4, "d15752" = 2, "d15754" = 8
hole "Díra1751" diameter "d15758" = 10; stored, may be unused: countersink angle "d15762" = 90 deg, drill point angle "d15764" = 0 deg; dims "d15756" = 76, "d15757" = 307, "d15759" = 6, "d15760" = 4, "d15761" = 2, "d15763" = 8
hole "Díra1752" diameter "d15767" = 10; stored, may be unused: countersink angle "d15771" = 90 deg, drill point angle "d15773" = 0 deg; dims "d15765" = 87, "d15766" = 307, "d15768" = 6, "d15769" = 4, "d15770" = 2, "d15772" = 8
hole "Díra1753" diameter "d15776" = 10; stored, may be unused: countersink angle "d15780" = 90 deg, drill point angle "d15782" = 0 deg; dims "d15774" = 98, "d15775" = 307, "d15777" = 6, "d15778" = 4, "d15779" = 2, "d15781" = 8
hole "Díra1754" diameter "d15785" = 10; stored, may be unused: countersink angle "d15789" = 90 deg, drill point angle "d15791" = 0 deg; dims "d15783" = 109, "d15784" = 307, "d15786" = 6, "d15787" = 4, "d15788" = 2, "d15790" = 8
hole "Díra1755" diameter "d15794" = 10; stored, may be unused: countersink angle "d15798" = 90 deg, drill point angle "d15800" = 0 deg; dims "d15792" = 120, "d15793" = 307, "d15795" = 6, "d15796" = 4, "d15797" = 2, "d15799" = 8
hole "Díra1756" diameter "d15803" = 10; stored, may be unused: countersink angle "d15807" = 90 deg, drill point angle "d15809" = 0 deg; dims "d15801" = 131, "d15802" = 307, "d15804" = 6, "d15805" = 4, "d15806" = 2, "d15808" = 8
hole "Díra1757" diameter "d15812" = 10; stored, may be unused: countersink angle "d15816" = 90 deg, drill point angle "d15818" = 0 deg; dims "d15810" = 142, "d15811" = 307, "d15813" = 6, "d15814" = 4, "d15815" = 2, "d15817" = 8
hole "Díra1758" diameter "d15821" = 10; stored, may be unused: countersink angle "d15825" = 90 deg, drill point angle "d15827" = 0 deg; dims "d15819" = 153, "d15820" = 307, "d15822" = 6, "d15823" = 4, "d15824" = 2, "d15826" = 8
hole "Díra1759" diameter "d15830" = 10; stored, may be unused: countersink angle "d15834" = 90 deg, drill point angle "d15836" = 0 deg; dims "d15828" = 164, "d15829" = 307, "d15831" = 6, "d15832" = 4, "d15833" = 2, "d15835" = 8
hole "Díra1760" diameter "d15839" = 10; stored, may be unused: countersink angle "d15843" = 90 deg, drill point angle "d15845" = 0 deg; dims "d15837" = 175, "d15838" = 307, "d15840" = 6, "d15841" = 4, "d15842" = 2, "d15844" = 8
hole "Díra1761" diameter "d15848" = 10; stored, may be unused: countersink angle "d15852" = 90 deg, drill point angle "d15854" = 0 deg; dims "d15846" = 186, "d15847" = 307, "d15849" = 6, "d15850" = 4, "d15851" = 2, "d15853" = 8
hole "Díra1762" diameter "d15857" = 10; stored, may be unused: countersink angle "d15861" = 90 deg, drill point angle "d15863" = 0 deg; dims "d15855" = 197, "d15856" = 307, "d15858" = 6, "d15859" = 4, "d15860" = 2, "d15862" = 8
hole "Díra1763" diameter "d15866" = 10; stored, may be unused: countersink angle "d15870" = 90 deg, drill point angle "d15872" = 0 deg; dims "d15864" = 208, "d15865" = 307, "d15867" = 6, "d15868" = 4, "d15869" = 2, "d15871" = 8
hole "Díra1764" diameter "d15875" = 10; stored, may be unused: countersink angle "d15879" = 90 deg, drill point angle "d15881" = 0 deg; dims "d15873" = 219, "d15874" = 307, "d15876" = 6, "d15877" = 4, "d15878" = 2, "d15880" = 8
hole "Díra1765" diameter "d15884" = 10; stored, may be unused: countersink angle "d15888" = 90 deg, drill point angle "d15890" = 0 deg; dims "d15882" = 230, "d15883" = 307, "d15885" = 6, "d15886" = 4, "d15887" = 2, "d15889" = 8
hole "Díra1766" diameter "d15893" = 10; stored, may be unused: countersink angle "d15897" = 90 deg, drill point angle "d15899" = 0 deg; dims "d15891" = 241, "d15892" = 307, "d15894" = 6, "d15895" = 4, "d15896" = 2, "d15898" = 8
hole "Díra1767" diameter "d15902" = 10; stored, may be unused: countersink angle "d15906" = 90 deg, drill point angle "d15908" = 0 deg; dims "d15900" = 252, "d15901" = 307, "d15903" = 6, "d15904" = 4, "d15905" = 2, "d15907" = 8
hole "Díra1768" diameter "d15911" = 10; stored, may be unused: countersink angle "d15915" = 90 deg, drill point angle "d15917" = 0 deg; dims "d15909" = 263, "d15910" = 307, "d15912" = 6, "d15913" = 4, "d15914" = 2, "d15916" = 8
hole "Díra1769" diameter "d15920" = 10; stored, may be unused: countersink angle "d15924" = 90 deg, drill point angle "d15926" = 0 deg; dims "d15918" = 274, "d15919" = 307, "d15921" = 6, "d15922" = 4, "d15923" = 2, "d15925" = 8
hole "Díra1770" diameter "d15929" = 10; stored, may be unused: countersink angle "d15933" = 90 deg, drill point angle "d15935" = 0 deg; dims "d15927" = 285, "d15928" = 307, "d15930" = 6, "d15931" = 4, "d15932" = 2, "d15934" = 8
hole "Díra1771" diameter "d15938" = 10; stored, may be unused: countersink angle "d15942" = 90 deg, drill point angle "d15944" = 0 deg; dims "d15936" = 296, "d15937" = 307, "d15939" = 6, "d15940" = 4, "d15941" = 2, "d15943" = 8
hole "Díra1772" diameter "d15947" = 10; stored, may be unused: countersink angle "d15951" = 90 deg, drill point angle "d15953" = 0 deg; dims "d15945" = 307, "d15946" = 307, "d15948" = 6, "d15949" = 4, "d15950" = 2, "d15952" = 8
hole "Díra1773" diameter "d15956" = 10; stored, may be unused: countersink angle "d15960" = 90 deg, drill point angle "d15962" = 0 deg; dims "d15954" = 318, "d15955" = 307, "d15957" = 6, "d15958" = 4, "d15959" = 2, "d15961" = 8
hole "Díra1774" diameter "d15965" = 9.92157; stored, may be unused: countersink angle "d15969" = 90 deg, drill point angle "d15971" = 0 deg; dims "d15963" = 329, "d15964" = 307, "d15966" = 6, "d15967" = 4, "d15968" = 2, "d15970" = 8
hole "Díra1775" diameter "d15974" = 5.17647; stored, may be unused: countersink angle "d15978" = 90 deg, drill point angle "d15980" = 0 deg; dims "d15972" = 340, "d15973" = 307, "d15975" = 6, "d15976" = 4, "d15977" = 2, "d15979" = 8
hole "Díra1776" diameter "d15983" = 3.01961; stored, may be unused: countersink angle "d15987" = 90 deg, drill point angle "d15989" = 0 deg; dims "d15981" = 10, "d15982" = 318, "d15984" = 6, "d15985" = 4, "d15986" = 2, "d15988" = 8
hole "Díra1777" diameter "d15992" = 5.28105; stored, may be unused: countersink angle "d15996" = 90 deg, drill point angle "d15998" = 0 deg; dims "d15990" = 21, "d15991" = 318, "d15993" = 6, "d15994" = 4, "d15995" = 2, "d15997" = 8
hole "Díra1778" diameter "d16001" = 8.16994; stored, may be unused: countersink angle "d16005" = 90 deg, drill point angle "d16007" = 0 deg; dims "d15999" = 32, "d16000" = 318, "d16002" = 6, "d16003" = 4, "d16004" = 2, "d16006" = 8
hole "Díra1779" diameter "d16010" = 8.90196; stored, may be unused: countersink angle "d16014" = 90 deg, drill point angle "d16016" = 0 deg; dims "d16008" = 43, "d16009" = 318, "d16011" = 6, "d16012" = 4, "d16013" = 2, "d16015" = 8
hole "Díra1780" diameter "d16019" = 9.41177; stored, may be unused: countersink angle "d16023" = 90 deg, drill point angle "d16025" = 0 deg; dims "d16017" = 54, "d16018" = 318, "d16020" = 6, "d16021" = 4, "d16022" = 2, "d16024" = 8
hole "Díra1781" diameter "d16028" = 10; stored, may be unused: countersink angle "d16032" = 90 deg, drill point angle "d16034" = 0 deg; dims "d16026" = 65, "d16027" = 318, "d16029" = 6, "d16030" = 4, "d16031" = 2, "d16033" = 8
hole "Díra1782" diameter "d16037" = 10; stored, may be unused: countersink angle "d16041" = 90 deg, drill point angle "d16043" = 0 deg; dims "d16035" = 76, "d16036" = 318, "d16038" = 6, "d16039" = 4, "d16040" = 2, "d16042" = 8
hole "Díra1783" diameter "d16046" = 10; stored, may be unused: countersink angle "d16050" = 90 deg, drill point angle "d16052" = 0 deg; dims "d16044" = 87, "d16045" = 318, "d16047" = 6, "d16048" = 4, "d16049" = 2, "d16051" = 8
hole "Díra1784" diameter "d16055" = 9.84314; stored, may be unused: countersink angle "d16059" = 90 deg, drill point angle "d16061" = 0 deg; dims "d16053" = 98, "d16054" = 318, "d16056" = 6, "d16057" = 4, "d16058" = 2, "d16060" = 8
hole "Díra1785" diameter "d16064" = 9.68628; stored, may be unused: countersink angle "d16068" = 90 deg, drill point angle "d16070" = 0 deg; dims "d16062" = 109, "d16063" = 318, "d16065" = 6, "d16066" = 4, "d16067" = 2, "d16069" = 8
hole "Díra1786" diameter "d16073" = 9.41177; stored, may be unused: countersink angle "d16077" = 90 deg, drill point angle "d16079" = 0 deg; dims "d16071" = 120, "d16072" = 318, "d16074" = 6, "d16075" = 4, "d16076" = 2, "d16078" = 8
hole "Díra1787" diameter "d16082" = 9.2549; stored, may be unused: countersink angle "d16086" = 90 deg, drill point angle "d16088" = 0 deg; dims "d16080" = 131, "d16081" = 318, "d16083" = 6, "d16084" = 4, "d16085" = 2, "d16087" = 8
hole "Díra1788" diameter "d16091" = 9.45098; stored, may be unused: countersink angle "d16095" = 90 deg, drill point angle "d16097" = 0 deg; dims "d16089" = 142, "d16090" = 318, "d16092" = 6, "d16093" = 4, "d16094" = 2, "d16096" = 8
hole "Díra1789" diameter "d16100" = 9.45098; stored, may be unused: countersink angle "d16104" = 90 deg, drill point angle "d16106" = 0 deg; dims "d16098" = 153, "d16099" = 318, "d16101" = 6, "d16102" = 4, "d16103" = 2, "d16105" = 8
hole "Díra1790" diameter "d16109" = 9.68628; stored, may be unused: countersink angle "d16113" = 90 deg, drill point angle "d16115" = 0 deg; dims "d16107" = 164, "d16108" = 318, "d16110" = 6, "d16111" = 4, "d16112" = 2, "d16114" = 8
hole "Díra1791" diameter "d16118" = 9.80392; stored, may be unused: countersink angle "d16122" = 90 deg, drill point angle "d16124" = 0 deg; dims "d16116" = 175, "d16117" = 318, "d16119" = 6, "d16120" = 4, "d16121" = 2, "d16123" = 8
hole "Díra1792" diameter "d16127" = 9.60784; stored, may be unused: countersink angle "d16131" = 90 deg, drill point angle "d16133" = 0 deg; dims "d16125" = 186, "d16126" = 318, "d16128" = 6, "d16129" = 4, "d16130" = 2, "d16132" = 8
